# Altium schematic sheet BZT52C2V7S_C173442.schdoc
size 127 x 101 mm
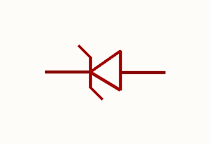
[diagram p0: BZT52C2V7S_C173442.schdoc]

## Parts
D?  bzt52c2v7s_c173442  [SOD-323_L1.8-W1.3-LS2.5-RD]  (value not drawn)

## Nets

Not connected (* = marked no-connect by the designer): D? 1 2

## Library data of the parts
D? = bzt52c2v7s_c173442: 二极管配置:1个独立式;稳压值(标称值):2.7V;稳压值(范围值):2.5V~2.9V;耗散功率(Pd):200mW;; Manufacturer: MDD(辰达半导体); AddInBom: yes; ModelId: db63db13d9e342eb939127d413d6200b; ModelTransform: 104.3305,51.181,0,0,0,0,0,-0.004,0; Diode Configuration: 1个独立式; Zener Voltage(Nom): 2.7V; Reverse Leakage Current (Ir): 120uA@1V; Pd - Power Dissipation: 200mW; Impedance(Zzt): 110Ω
